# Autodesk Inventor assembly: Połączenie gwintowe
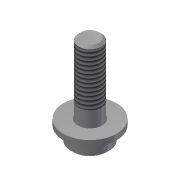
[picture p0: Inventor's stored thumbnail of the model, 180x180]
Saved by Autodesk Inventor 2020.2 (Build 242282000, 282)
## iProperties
Manager: www.cadconsulting.pl
Company: Fabian Stasiak CAD Consulting
ClientObjectVersion: 1
Created: 2011-01
Part Number: Połączenie gwintowe
Document SubType Name: Assembly
Designer: F.Stasiak
Author: F.Stasiak
Subject: Zbiór ćwiczeń. Autodesk Inventor 2020. Kurs podstawowy
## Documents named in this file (3)
- C:\2020_Kurs_podstawowy\R6 Zespoły\Kolizja\100-000\Design Accelerator\Połączenie gwintowe8.iam
- C:\2020_Kurs_podstawowy\Zasoby\Content Center Files\pl-PL\DIN 6796\DIN 6796 - 6.ipt
- C:\2020_Kurs_podstawowy\Zasoby\Content Center Files\pl-PL\DIN 6912\DIN 6912 - M6 x 20.ipt
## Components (2 placed, 2 different names)
1. DIN 6796 6:1
2. DIN 6912 M6 x 20:1
